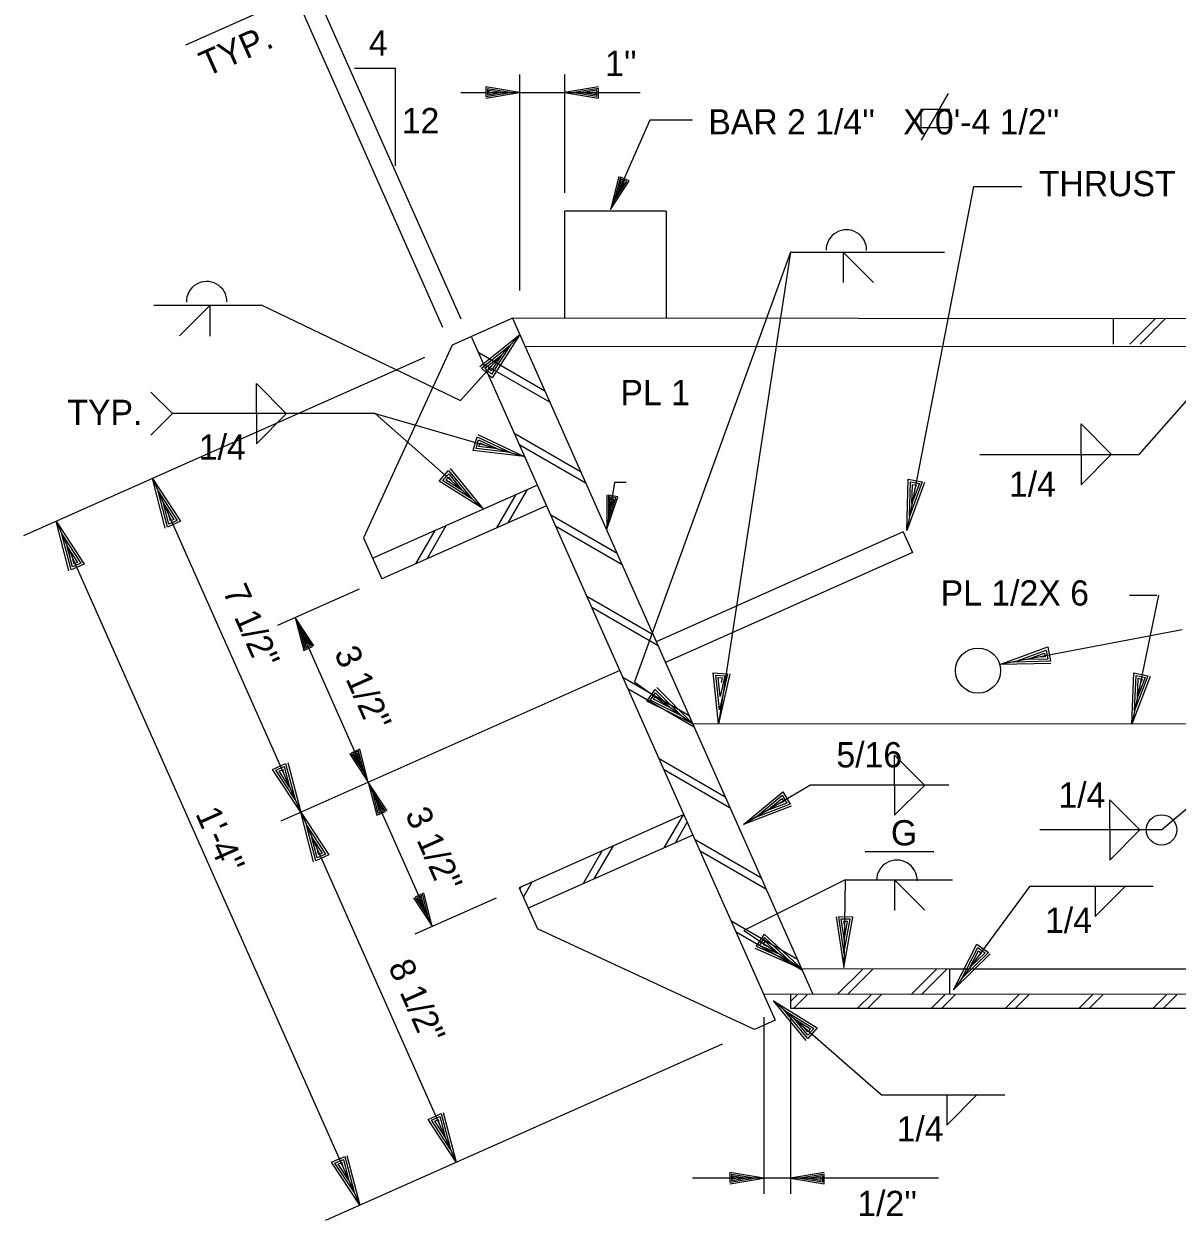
# Model space of a CAD drawing. Extents: x 0.1 to 13.5, y 0.1 to 9.5.
# Drawn here: x 5.261 to 7.395, y 4.107 to 6.319 of the extents above; entities that cross this region are included whole.
import ezdxf

# ---------------------------------------------------------------- set-up
doc = ezdxf.new("R2010")
doc.units = 0
for name, color, linetype in [('Level 1', 7, 'Continuous'), ('Level 25', 7, 'Continuous'), ('Level 3', 7, 'Continuous'), ('Level 44', 7, 'Continuous'), ('Level 50', 7, 'Continuous')]:
    doc.layers.add(name, color=color, linetype=linetype)

msp = doc.modelspace()

# ---------------------------------------------------------------- linework, layer by layer
at = {"layer": 'Level 1'}
for p, q in [((5.8729, 6.2376), (5.9477, 6.2376)), ((6.0695, 6.1924), (6.1782, 6.1924)), ((6.1782, 6.1924), (6.2615, 6.1924)), ((6.2615, 6.1924), (6.4012, 6.1924))]:
    msp.add_line(p, q, dxfattribs=at)
at = {"layer": 'Level 25'}
for p, q in [((5.7883, 6.406), (6.0693, 5.7737)), ((5.7546, 6.391), (6.0356, 5.7587)), ((5.7636, 6.3708), (5.5597, 6.2802)), ((5.9477, 6.2376), (5.9477, 6.0566)), ((6.1782, 6.2255), (6.1782, 5.826)), ((6.2615, 6.2255), (6.2615, 6.007)), ((6.971, 6.1906), (6.9213, 6.1045)), ((6.9727, 6.1613), (6.9204, 6.1613)), ((6.9204, 6.1613), (6.9204, 6.1271)), ((6.9727, 6.1613), (6.9727, 6.1271)), ((6.9727, 6.1271), (6.9204, 6.1271)), ((6.2615, 5.973), (6.2615, 5.7748)), ((6.449, 5.9729), (6.2615, 5.973)), ((6.449, 5.973), (6.449, 5.7747)), ((6.6791, 5.8972), (6.9643, 5.8972)), ((6.7767, 5.8972), (6.7767, 5.8409)), ((6.7767, 5.8972), (6.8327, 5.8412)), ((5.7026, 5.7983), (5.5013, 5.7983)), ((5.605, 5.7983), (5.5491, 5.7424)), ((5.605, 5.7983), (5.605, 5.7421)), ((6.1652, 5.7749), (6.0531, 5.7251)), ((6.1652, 5.7749), (6.7209, 4.5246)), ((8.6386, 5.7734), (6.1652, 5.7749)), ((7.2761, 5.7742), (7.2761, 5.7273)), ((7.3074, 5.727), (7.3546, 5.7742)), ((7.3263, 5.727), (7.3734, 5.7742)), ((6.0894, 5.7402), (6.6511, 4.4765)), ((6.2251, 5.6402), (6.1024, 5.711)), ((8.6385, 5.7213), (6.1883, 5.7228)), ((7.3243, 5.5232), (7.493, 5.7143)), ((5.261, 5.373), (6.0028, 5.7028)), ((6.2343, 5.6195), (6.1116, 5.6903)), ((5.6911, 5.6541), (5.747, 5.5983)), ((5.6911, 5.5979), (5.6911, 5.6541)), ((5.5357, 5.5985), (5.4958, 5.6383)), ((5.5357, 5.5985), (5.4958, 5.5587)), ((5.9108, 5.5985), (5.5357, 5.5985)), ((5.6911, 5.599), (5.6911, 5.5428)), ((5.6911, 5.5428), (5.747, 5.5987)), ((5.9108, 5.5985), (6.1865, 5.5193)), ((5.9108, 5.5985), (6.1098, 5.4234)), ((7.2169, 5.5795), (7.2728, 5.5236)), ((7.2169, 5.5232), (7.2169, 5.5795)), ((6.2918, 5.49), (6.1691, 5.5609)), ((6.301, 5.4693), (6.1783, 5.5401)), ((6.1615, 5.5265), (6.1615, 5.5265)), ((6.1865, 5.5193), (6.1865, 5.5193)), ((7.0294, 5.5232), (7.3243, 5.5232)), ((7.2169, 5.5232), (7.2169, 5.467)), ((7.2169, 5.467), (7.2728, 5.5229)), ((5.4988, 5.4787), (5.7731, 4.8614)), ((6.2111, 5.4664), (5.9065, 5.3311)), ((6.1363, 5.3876), (6.1718, 5.4489)), ((6.1571, 5.3968), (6.1925, 5.4582)), ((6.228, 5.4283), (5.9234, 5.293)), ((6.0903, 5.4406), (6.0903, 5.4406)), ((6.1098, 5.4234), (6.1098, 5.4234)), ((5.3204, 5.3994), (5.8824, 4.1348)), ((6.3585, 5.3399), (6.2359, 5.4107)), ((5.9862, 5.3209), (6.0216, 5.3822)), ((6.0069, 5.3301), (6.0423, 5.3914)), ((6.3677, 5.3192), (6.2451, 5.39)), ((6.888, 5.3797), (6.4311, 5.1766)), ((6.888, 5.3797), (6.9049, 5.3416)), ((5.8896, 5.3691), (5.9234, 5.293)), ((6.9049, 5.3416), (6.448, 5.1385)), ((5.9065, 5.3311), (5.9065, 5.3311)), ((5.9234, 5.293), (5.9234, 5.293)), ((5.731, 5.2075), (5.8816, 5.2744)), ((6.4253, 5.1897), (6.3026, 5.2606)), ((5.7628, 5.2216), (5.8982, 4.917)), ((6.4345, 5.169), (6.3118, 5.2399)), ((6.3634, 5.1237), (5.7363, 4.845)), ((6.492, 5.0396), (6.3693, 5.1104)), ((6.5012, 5.0189), (6.3785, 5.0897)), ((6.391, 5.1024), (6.4986, 5.0247)), ((6.5478, 5.0507), (6.5478, 5.0507)), ((6.4775, 5.0399), (6.4775, 5.0399)), ((7.5053, 5.0241), (6.4986, 5.0247)), ((6.4986, 5.0247), (6.4986, 5.0247)), ((6.5463, 5.0247), (6.5463, 5.0247)), ((6.5587, 4.8894), (6.4361, 4.9603)), ((6.8717, 4.967), (6.9276, 4.9111)), ((6.8717, 4.9107), (6.8717, 4.967)), ((6.5679, 4.8687), (6.4453, 4.9396)), ((7.3658, 4.8287), (7.5035, 4.9457)), ((5.8982, 4.917), (5.8982, 4.917)), ((5.8982, 4.917), (6.0166, 4.6504)), ((6.7162, 4.9113), (6.5922, 4.8387)), ((6.9723, 4.9113), (6.7162, 4.9113)), ((6.9723, 4.9113), (6.7162, 4.9113)), ((6.8717, 4.9119), (6.8717, 4.8557)), ((6.8717, 4.8557), (6.9276, 4.9115)), ((7.2699, 4.8843), (7.3257, 4.8285)), ((7.2699, 4.8281), (7.2699, 4.8843)), ((5.7731, 4.8614), (6.0608, 4.2141)), ((6.4819, 4.8572), (6.1773, 4.7218)), ((6.4457, 4.7955), (6.4811, 4.8568)), ((6.6147, 4.8518), (6.6147, 4.8518)), ((6.4664, 4.8047), (6.4883, 4.8427)), ((6.5922, 4.8387), (6.5922, 4.8387)), ((7.3658, 4.8287), (7.1404, 4.8287)), ((7.3658, 4.8287), (7.2195, 4.8287)), ((7.2699, 4.8293), (7.2699, 4.773)), ((7.2699, 4.773), (7.3257, 4.8289)), ((6.4988, 4.8191), (6.1942, 4.6838)), ((6.6255, 4.7393), (6.5028, 4.8101)), ((6.2955, 4.7288), (6.3309, 4.7901)), ((6.3162, 4.738), (6.3516, 4.7993)), ((6.6347, 4.7186), (6.512, 4.7894)), ((6.9445, 4.788), (6.8177, 4.788)), ((6.7802, 4.7362), (6.5927, 4.6424)), ((6.7802, 4.7362), (6.778, 4.574)), ((6.7802, 4.7362), (6.9788, 4.7362)), ((6.8717, 4.7362), (6.8717, 4.6799)), ((6.8717, 4.7362), (6.9277, 4.6802)), ((6.1772, 4.7218), (6.2111, 4.6457)), ((6.1773, 4.7218), (6.1773, 4.7218)), ((6.1784, 4.7193), (6.1808, 4.7234)), ((6.1851, 4.7042), (6.2015, 4.7326)), ((7.1219, 4.7246), (6.9812, 4.533)), ((7.1219, 4.7246), (7.3503, 4.7246)), ((7.2429, 4.7246), (7.2429, 4.6683)), ((7.2429, 4.6683), (7.2988, 4.7242)), ((5.9849, 4.6363), (6.1354, 4.7033)), ((6.0166, 4.6504), (6.0166, 4.6504)), ((6.6922, 4.5891), (6.5695, 4.66)), ((6.7014, 4.5684), (6.5787, 4.6393)), ((6.5927, 4.6424), (6.7, 4.5715)), ((6.6783, 4.5858), (6.6783, 4.5858)), ((6.7783, 4.6), (6.7783, 4.6)), ((6.9737, 4.5713), (6.7, 4.5715)), ((6.7, 4.5715), (6.7, 4.5715)), ((6.7007, 4.57), (6.7021, 4.5715)), ((6.7663, 4.5246), (6.8131, 4.5714)), ((6.778, 4.574), (6.778, 4.574)), ((6.7851, 4.5245), (6.8319, 4.5714)), ((6.9029, 4.5245), (6.9497, 4.5713)), ((6.9217, 4.5245), (6.9686, 4.5713)), ((8.6378, 4.5703), (6.9737, 4.5713)), ((6.9737, 4.5713), (6.9737, 4.5244)), ((6.9966, 4.5539), (6.9966, 4.5539)), ((8.6378, 4.5234), (6.6297, 4.5246)), ((6.6792, 4.5248), (6.6792, 4.4987)), ((6.6792, 4.5111), (6.6915, 4.5234)), ((6.6857, 4.4987), (6.7104, 4.5234)), ((6.8035, 4.4987), (6.8283, 4.5234)), ((6.8224, 4.4987), (6.8471, 4.5234)), ((6.9402, 4.4987), (6.965, 4.5234)), ((6.9591, 4.4987), (6.9838, 4.5234)), ((6.9812, 4.533), (6.9812, 4.533)), ((7.0769, 4.4987), (7.1017, 4.5234)), ((7.0958, 4.4987), (7.1205, 4.5234)), ((7.2137, 4.4987), (7.2384, 4.5234)), ((7.2325, 4.4987), (7.2572, 4.5234)), ((7.3504, 4.4987), (7.3751, 4.5234)), ((7.3692, 4.4987), (7.3939, 4.5234)), ((8.6378, 4.4974), (6.6792, 4.4986)), ((6.6511, 4.4765), (6.613, 4.4595)), ((6.6297, 4.4824), (6.6297, 4.1558)), ((6.6792, 4.4824), (6.6792, 4.1558)), ((5.8199, 4.1071), (6.5533, 4.433)), ((6.8473, 4.3389), (7.0756, 4.3389)), ((6.9683, 4.3389), (6.9683, 4.2826)), ((6.9683, 4.2826), (7.0241, 4.3385)), ((6.6297, 4.1846), (6.4981, 4.1847)), ((6.6297, 4.1846), (6.6297, 4.1846)), ((6.6792, 4.1845), (6.6297, 4.1846)), ((6.6792, 4.1845), (6.6792, 4.1845)), ((6.9533, 4.1844), (6.6792, 4.1845))]:
    msp.add_line(p, q, dxfattribs=at)
for points in [[(6.1009, 5.56), (6.1865, 5.5193), (6.0923, 5.5302), (6.0996, 5.5557), (6.1615, 5.5265), (6.0976, 5.5339), (6.1023, 5.5503), (6.1375, 5.5334), (6.1028, 5.5376), (6.1047, 5.5444), (6.1125, 5.5406)], [(6.0498, 5.4968), (6.1098, 5.4234), (6.0293, 5.4735), (6.0468, 5.4934), (6.0903, 5.4406), (6.0356, 5.4746), (6.0469, 5.4874), (6.0715, 5.4571), (6.0419, 5.4758), (6.0466, 5.481), (6.052, 5.4743)], [(6.5672, 5.1171), (6.5463, 5.0247), (6.5363, 5.1189), (6.5627, 5.1174), (6.5478, 5.0507), (6.541, 5.1147), (6.558, 5.1137), (6.5493, 5.0756), (6.5458, 5.1104), (6.5528, 5.11), (6.5508, 5.1016)], [(6.4319, 5.092), (6.4986, 5.0247), (6.4137, 5.0669), (6.4292, 5.0884), (6.4775, 5.0399), (6.4199, 5.0686), (6.4298, 5.0824), (6.4573, 5.0546), (6.4261, 5.0703), (6.4302, 5.076), (6.4362, 5.0698)], [(6.6808, 4.8726), (6.5922, 4.8387), (6.6651, 4.8993), (6.6785, 4.8764), (6.6147, 4.8518), (6.6641, 4.893), (6.6727, 4.8783), (6.6362, 4.8644), (6.6632, 4.8866), (6.6668, 4.8806), (6.6587, 4.8776)], [(6.7638, 4.6677), (6.778, 4.574), (6.7948, 4.6673), (6.7683, 4.6676), (6.7783, 4.6), (6.7897, 4.6633), (6.7727, 4.6636), (6.7787, 4.625), (6.7846, 4.6594), (6.7776, 4.6595), (6.779, 4.651)], [(6.6135, 4.6101), (6.7, 4.5715), (6.6306, 4.6359), (6.616, 4.6138), (6.6783, 4.5858), (6.6311, 4.6296), (6.6218, 4.6154), (6.6575, 4.5996), (6.6317, 4.6232), (6.6279, 4.6173), (6.6358, 4.6139)], [(7.049, 4.5992), (6.9812, 4.533), (7.024, 4.6175), (7.0454, 4.6018), (6.9966, 4.5539), (7.0257, 4.6113), (7.0394, 4.6013), (7.0113, 4.5741), (7.0273, 4.6051), (7.033, 4.601), (7.0267, 4.595)]]:
    msp.add_lwpolyline(points, dxfattribs=at)
for centre, radius in [((7.0263, 5.1233), 0.0417), ((7.3658, 4.8287), 0.0281)]:
    msp.add_circle(centre, radius, dxfattribs=at)
for centre, start, end in [((6.7827, 5.9011), 358.4208, 180), ((5.5991, 5.8055), 0, 181.5792), ((6.8761, 4.7354), 358.4208, 180)]:
    msp.add_arc(centre, 0.0375, start, end, dxfattribs=at)
at = {"layer": 'Level 3'}
for p, q in [((6.3461, 5.9761), (6.3461, 5.9761)), ((6.3531, 5.992), (6.3531, 5.992)), ((6.3423, 5.402), (6.3423, 5.402)), ((6.3394, 5.3849), (6.3394, 5.3849))]:
    msp.add_line(p, q, dxfattribs=at)
for points in [[(6.4983, 6.1416), (6.4189, 6.1416), (6.3461, 5.9761)], [(6.3617, 6.0373), (6.3461, 5.9761), (6.3806, 6.029), (6.3645, 6.0361), (6.3531, 5.992), (6.3765, 6.0279), (6.3661, 6.0325), (6.3598, 6.0072), (6.3724, 6.0268), (6.3681, 6.0287), (6.3668, 6.0231)], [(6.3754, 5.4713), (6.3538, 5.4713), (6.3394, 5.3849)], [(6.3395, 5.4481), (6.3394, 5.3849), (6.3599, 5.4447), (6.3424, 5.4476), (6.3423, 5.402), (6.3561, 5.4426), (6.345, 5.4445), (6.345, 5.4185), (6.3524, 5.4406), (6.3478, 5.4413), (6.3479, 5.4356)]]:
    msp.add_lwpolyline(points, dxfattribs=at)
at = {"layer": 'Level 44'}
for p, q in [((7.0182, 6.0188), (6.8943, 5.3825)), ((7.0182, 6.0188), (7.1075, 6.0188)), ((6.6791, 5.8972), (6.391, 5.1024)), ((6.6791, 5.8972), (6.5463, 5.0247)), ((5.7026, 5.7983), (6.0685, 5.6229)), ((6.0685, 5.6229), (6.1786, 5.7448)), ((6.0531, 5.7251), (5.8896, 5.3691)), ((7.3066, 5.2626), (7.3572, 5.2626)), ((7.3604, 5.2626), (7.3108, 5.0242)), ((7.4042, 5.1986), (7.0664, 5.1344)), ((6.613, 4.4595), (6.2111, 4.6457)), ((6.8473, 4.3389), (6.6481, 4.5126))]:
    msp.add_line(p, q, dxfattribs=at)
at = {"layer": 'Level 50'}
for p, q in [((6.1609, 6.1924), (6.1609, 6.1924)), ((6.1782, 6.1924), (6.1782, 6.1924)), ((6.2615, 6.1924), (6.2615, 6.1924)), ((6.2789, 6.1924), (6.2789, 6.1924)), ((6.1786, 5.7448), (6.1786, 5.7448)), ((6.1612, 5.7255), (6.1612, 5.7255)), ((5.4988, 5.4787), (5.4988, 5.4787)), ((5.5093, 5.4549), (5.5093, 5.4549)), ((5.3204, 5.3994), (5.3204, 5.3994)), ((5.3204, 5.3994), (5.3204, 5.3994)), ((6.8993, 5.408), (6.8993, 5.408)), ((6.8943, 5.3825), (6.8943, 5.3825)), ((5.3309, 5.3757), (5.3309, 5.3757)), ((5.3309, 5.3757), (5.3309, 5.3757)), ((5.7628, 5.2216), (5.7628, 5.2216)), ((5.7698, 5.2058), (5.7698, 5.2058)), ((7.0664, 5.1344), (7.0664, 5.1344)), ((7.092, 5.1392), (7.092, 5.1392)), ((7.3161, 5.0497), (7.3161, 5.0497)), ((7.3108, 5.0242), (7.3108, 5.0242)), ((5.8911, 4.9328), (5.8911, 4.9328)), ((5.8982, 4.917), (5.8982, 4.917)), ((5.8982, 4.917), (5.8982, 4.917)), ((5.9052, 4.9011), (5.9052, 4.9011)), ((5.7626, 4.8852), (5.7626, 4.8852)), ((5.7731, 4.8614), (5.7731, 4.8614)), ((5.7731, 4.8614), (5.7731, 4.8614)), ((5.7837, 4.8376), (5.7837, 4.8376)), ((6.0096, 4.6663), (6.0096, 4.6663)), ((6.0166, 4.6504), (6.0166, 4.6504)), ((6.6481, 4.5126), (6.6481, 4.5126)), ((6.6677, 4.4955), (6.6677, 4.4955)), ((6.0503, 4.2379), (6.0503, 4.2379)), ((6.0608, 4.2141), (6.0608, 4.2141)), ((6.6123, 4.1846), (6.6123, 4.1846)), ((6.6297, 4.1846), (6.6297, 4.1846)), ((6.6792, 4.1845), (6.6792, 4.1845)), ((6.6965, 4.1845), (6.6965, 4.1845)), ((5.8719, 4.1586), (5.8719, 4.1586)), ((5.8824, 4.1348), (5.8824, 4.1348))]:
    msp.add_line(p, q, dxfattribs=at)
for points in [[(6.1159, 6.182), (6.1782, 6.1924), (6.1159, 6.2027), (6.1159, 6.185), (6.1609, 6.1924), (6.1185, 6.1994), (6.1185, 6.188), (6.1442, 6.1924), (6.1212, 6.196), (6.1212, 6.1914), (6.1269, 6.1924)], [(6.3239, 6.2027), (6.2615, 6.1924), (6.3239, 6.182), (6.3239, 6.1997), (6.2789, 6.1924), (6.3212, 6.1854), (6.3212, 6.1967), (6.2955, 6.1924), (6.3185, 6.1887), (6.3185, 6.1934), (6.3129, 6.1924)], [(6.1044, 5.6858), (6.1786, 5.7448), (6.1274, 5.665), (6.1078, 5.6828), (6.1612, 5.7255), (6.1264, 5.6713), (6.1138, 5.6827), (6.1444, 5.7069), (6.1254, 5.6776), (6.1202, 5.6823), (6.127, 5.6876)], [(5.5226, 5.387), (5.4988, 5.4787), (5.5509, 5.3996), (5.5267, 5.3888), (5.5093, 5.4549), (5.5447, 5.4012), (5.5292, 5.3943), (5.5195, 5.4321), (5.5385, 5.4028), (5.5321, 5.4), (5.53, 5.4083)], [(6.9274, 5.4713), (6.8943, 5.3825), (6.8969, 5.4772), (6.923, 5.4722), (6.8993, 5.408), (6.9011, 5.4723), (6.9178, 5.4691), (6.904, 5.4326), (6.9052, 5.4675), (6.9121, 5.4661), (6.909, 5.4581)], [(5.3442, 5.3077), (5.3204, 5.3994), (5.3725, 5.3203), (5.3483, 5.3095), (5.3309, 5.3757), (5.3663, 5.3219), (5.3508, 5.315), (5.3411, 5.3528), (5.3601, 5.3235), (5.3537, 5.3207), (5.3516, 5.3291)], [(5.3442, 5.3077), (5.3204, 5.3994), (5.3725, 5.3203), (5.3483, 5.3095), (5.3309, 5.3757), (5.3663, 5.3219), (5.3508, 5.315), (5.3411, 5.3528), (5.3601, 5.3235), (5.3537, 5.3207), (5.3516, 5.3291)], [(5.7975, 5.1688), (5.7628, 5.2216), (5.7787, 5.1604), (5.7948, 5.1676), (5.7698, 5.2058), (5.7806, 5.1642), (5.791, 5.1688), (5.7766, 5.1905), (5.7826, 5.168), (5.7868, 5.1699), (5.7836, 5.1747)], [(7.1612, 5.1366), (7.0664, 5.1344), (7.1554, 5.167), (7.1603, 5.141), (7.092, 5.1392), (7.1524, 5.1614), (7.1556, 5.1447), (7.1165, 5.1439), (7.1494, 5.1557), (7.1507, 5.1489), (7.1421, 5.1487)], [(7.345, 5.1126), (7.3108, 5.0242), (7.3147, 5.1189), (7.3406, 5.1135), (7.3161, 5.0497), (7.3188, 5.114), (7.3354, 5.1105), (7.3212, 5.0742), (7.3228, 5.1091), (7.3297, 5.1076), (7.3265, 5.0996)], [(5.8634, 4.9697), (5.8982, 4.917), (5.8823, 4.9781), (5.8662, 4.9709), (5.8911, 4.9328), (5.8803, 4.9743), (5.87, 4.9697), (5.8844, 4.948), (5.8784, 4.9705), (5.8741, 4.9686), (5.8773, 4.9639)], [(5.7493, 4.9531), (5.7731, 4.8614), (5.721, 4.9405), (5.7452, 4.9513), (5.7626, 4.8852), (5.7272, 4.9389), (5.7427, 4.9458), (5.7524, 4.908), (5.7334, 4.9373), (5.7398, 4.9401), (5.7419, 4.9318)], [(5.9329, 4.8642), (5.8982, 4.917), (5.9141, 4.8558), (5.9302, 4.863), (5.9052, 4.9011), (5.916, 4.8596), (5.9264, 4.8642), (5.912, 4.8859), (5.918, 4.8634), (5.9222, 4.8653), (5.919, 4.8701)], [(5.797, 4.7697), (5.7731, 4.8614), (5.8253, 4.7823), (5.8011, 4.7715), (5.7837, 4.8376), (5.8191, 4.7839), (5.8036, 4.777), (5.7939, 4.8148), (5.8129, 4.7855), (5.8065, 4.7827), (5.8044, 4.791)], [(5.9819, 4.7032), (6.0166, 4.6504), (6.0008, 4.7116), (5.9846, 4.7044), (6.0096, 4.6663), (5.9988, 4.7078), (5.9884, 4.7032), (6.0028, 4.6815), (5.9968, 4.704), (5.9926, 4.7021), (5.9958, 4.6974)], [(6.7084, 4.4394), (6.6481, 4.5126), (6.7288, 4.4628), (6.7114, 4.4428), (6.6677, 4.4955), (6.7225, 4.4616), (6.7113, 4.4488), (6.6866, 4.479), (6.7162, 4.4605), (6.7116, 4.4552), (6.7061, 4.4619)], [(6.037, 4.3059), (6.0608, 4.2141), (6.0087, 4.2933), (6.0329, 4.304), (6.0503, 4.2379), (6.0149, 4.2917), (6.0304, 4.2986), (6.0401, 4.2607), (6.0211, 4.29), (6.0275, 4.2929), (6.0296, 4.2845)], [(5.8586, 4.2266), (5.8824, 4.1348), (5.8303, 4.214), (5.8545, 4.2248), (5.8719, 4.1586), (5.8365, 4.2124), (5.852, 4.2193), (5.8617, 4.1814), (5.8427, 4.2107), (5.8491, 4.2136), (5.8512, 4.2052)], [(6.5673, 4.1743), (6.6297, 4.1846), (6.5673, 4.1949), (6.5673, 4.1773), (6.6123, 4.1846), (6.57, 4.1916), (6.57, 4.1803), (6.5957, 4.1846), (6.5727, 4.1883), (6.5727, 4.1836), (6.5783, 4.1846)], [(6.7416, 4.1948), (6.6792, 4.1845), (6.7415, 4.1742), (6.7415, 4.1918), (6.6965, 4.1845), (6.7389, 4.1775), (6.7389, 4.1888), (6.7132, 4.1845), (6.7362, 4.1808), (6.7362, 4.1855), (6.7305, 4.1845)]]:
    msp.add_lwpolyline(points, dxfattribs=at)

# ---------------------------------------------------------------- texts
at = {"layer": 'Level 1'}
for p in [(5.5846, 5.5133), (7.0835, 5.4448), (7.1751, 4.8698), (7.1503, 4.6383), (6.8757, 4.2525)]:
    msp.add_text('1/4', height=0.0467, dxfattribs=at).set_placement(p)
at = {"layer": 'Level 25'}
for s, rotation, p in [('TYP.', 23.9622, (5.5991, 6.2211)), ('7 1/2"', 293.9641, (5.628, 5.2704)), ("3 1/2''", 293.9636, (5.8343, 5.1561)), ("1'-4''", 293.9642, (5.5776, 4.8589)), ("3 1/2''", 293.9633, (5.9656, 4.8581)), ('8 1/2"', 293.9641, (5.9343, 4.5765)), ("1/2''", 359.9653, (6.8029, 4.1145))]:
    msp.add_text(s, height=0.0467, rotation=rotation, dxfattribs=at).set_placement(p)
for s, height, p in [('4', 0.0467, (5.8994, 6.2609)), ("1''", 0.0467, (6.3363, 6.2231)), ('12', 0.0467, (5.9601, 6.1171)), ("BAR 2 1/4''   X 0'-4 1/2''", 0.046698, (6.5272, 6.1149)), ('THRUST PL 1/2X 6', 0.046698, (7.1387, 6.0007)), ('PL 1', 0.0467, (6.3647, 5.6142)), ('TYP.', 0.0467, (5.3414, 5.5775)), ('PL 1/2X 6', 0.0467, (6.9572, 5.2436)), ('5/16', 0.0467, (6.7643, 4.9443)), ('G', 0.0467, (6.8651, 4.8))]:
    msp.add_text(s, height=height, dxfattribs=at).set_placement(p)

doc.saveas('drawing.dxf')
